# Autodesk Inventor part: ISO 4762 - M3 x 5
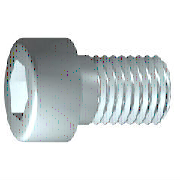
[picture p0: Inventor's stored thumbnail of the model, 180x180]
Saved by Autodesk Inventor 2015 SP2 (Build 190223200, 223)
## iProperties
IsCustomPart: 0
Created: 2012-02
Part Number: ISO 4762 - M3 x 5
Material: Edelstahl, 440C
Description: Innensechskantschraube
Document SubType Name: Modeling
Standard: ISO 4762
Designer: rmaryll
Standard Revision: Fourth edition 2004-03-01
Standards Organization: ISO
Language: de-DE
Size Designation: M3 x 5
Categories: <MemberInstance><Categories><Category DisplayName="Verbindungselemente" InternalName="e4da775c-781d-43d5-af7c-5136215cf5a6" Mnemonic="FSTN"><Category DisplayNam
Density: 7.75 g/cm^3
Appearance: Halbpoliert
Author: rmaryll
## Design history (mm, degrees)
sketch "Skizze1"
  geometry: L1 (-0.867, 0)-(5, 0); L2 (5, 0)-(5, 1.5); L3 (5, 1.5)-(1.25, 1.5); L4 (1.25, 1.5)-(0.943, 1.5); L5 (0.943, 1.5)-(0, 1.5); L6 (0, 1.5)-(0, 2.75); L7 (0, 2.75)-(-3, 2.75); L8 (-3, 2.75)-(-3, 1.443); L9 (-3, 1.443)-(-1.7, 1.443); L10 (-1.7, 1.443)-(-0.867, 0); L11 (-4.6, 0)-(6.6, 0) reference; L12 (0, -0.55)-(0, 3.3) reference; L13 (1.25, 1.5)-(0, 1.5)
  constraints: 22 end point, 6 parallel, 2 collinear, 2 perpendicular, 1 horizontal, 1 point on line
  dimensions: "d1" = 3.75 distance from line of L3.end L2 (= GEL); "d2" = 0.30683 distance of L4.end L3.end (computed from GAL); "d3" = 3 distance between parallel lines of L8 L6 (= KOH); "d4" = 1.3 distance of L8.end L9.end (= INTI); "d5" = 60 deg angle of L10 L1; "d6" = 3 diameter of L3 L1 (= GD); "d7" = 3 diameter of L5 L1 (= BDM); "d8" = 2.88675 diameter of L9 L1 (= 1.1547 x SW); "d9" = 5.5 diameter of L7 L1 (= KOD); "d26" = 5 distance between parallel lines of L12 L2 (= NLG)
revolve "Körper" sketch "Skizze1" stored, may be unused: angle "d10" = 90 deg
sketch "Skizze2"
  geometry: L1 (0, -3.85)-(0, 3.85) reference; L2 (-3.85, 0)-(3.85, 0) reference; L3 (1.443, 0)-(0.722, -1.25); L4 (0.722, -1.25)-(-0.722, -1.25); L5 (-0.722, -1.25)-(-1.443, 0); L6 (-1.443, 0)-(-0.722, 1.25); L7 (-0.722, 1.25)-(0.722, 1.25); L8 (0.722, 1.25)-(1.443, 0); 2 further points
  constraints: 12 end point, 1 coincident, 1 horizontal alignment, 1 point on line, 12 other
extrude "Loch" join sketch "Skizze2" stored distance "d11" = 10; taper "d12" = 0 deg
workplane "Work Plane1"
fillet "Fillet2" dims "d30" = 0.1 (= R)
body "Solid1"
fillet "Rundung1" dims "d17" = 0.3 (= RR)
feature "Gewinde" dims "d13" = 3.75 (= GEL), "d14" = 0
chamfer "Fase1" distance "d15" = 0.30673 (= -0.5 x SPD + 0.5 x GD); stored, may be unused: second distance "d16" = 0.30673 (= GUL), angle "d27" = 45 deg
other parameters: "GD" = 3 [user parameter; used in 2 equation terms], "NLG" = 5 [user parameter; used in 1 equation term], "GEL" = 3.75 [user parameter; used in 2 equation terms], "KOD" = 5.5 [user parameter; used in 1 equation term], "KOH" = 3 [user parameter; used in 1 equation term], "INTI" = 1.3 [user parameter; used in 1 equation term], "GAL" = 0.30673 (= 0.61345 x PTC) [user parameter; used in 1 equation term], "GUL" = 0.30673 (= 0.61345 x PTC) [user parameter; used in 1 equation term], "BDM" = 3 (= NND) [user parameter; used in 1 equation term], "SW" = 2.5 [user parameter; used in 2 equation terms], "RR" = 0.3 [user parameter; used in 1 equation term], "SPD" = 2.38655 (= NND - 1.2269 x PTC) [user parameter; used in 1 equation term], "d19" = 0, "d28" = 0, "d29" = 0, "R" = 0.1 [user parameter; used in 1 equation term], "TOA" = 30 deg [user parameter], "GD1" = 2.38655 (= THREADDIA - 1.2269 x PTC) [user parameter], "THREADDIA" = 3 [user parameter; used in 1 equation term], "FAWI" = 45 deg [user parameter], "PTC" = 0.5 [user parameter; used in 5 equation terms], "NND" = 3 [user parameter; used in 2 equation terms], "E0" = 2.8875 (= 1.155 x SW) [user parameter]
